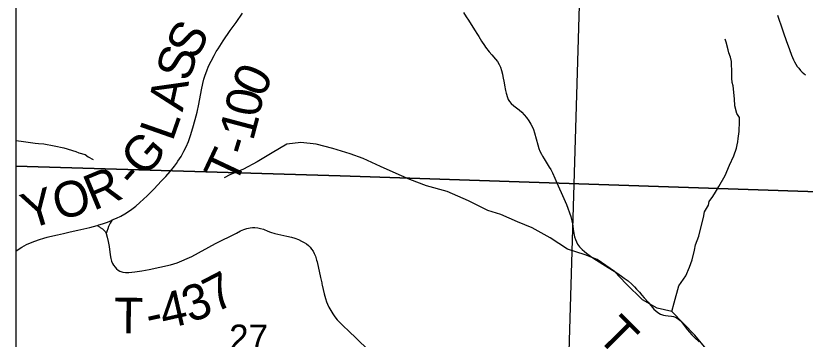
# Model space of a CAD drawing. Extents: x 6.3 to 40.3, y 9 to 31.
# Drawn here: x 8.445 to 9.705, y 27.639 to 28.156 of the extents above; entities that cross this region are included whole.
import ezdxf

# ---------------------------------------------------------------- set-up
doc = ezdxf.new("R2010")
doc.units = 0
for name, color, linetype in [('Default', 7, 'Continuous'), ('GM_X_Corporation', 7, 'Continuous'), ('GM_X_Minor_River', 7, 'Continuous'), ('GM_X_Section', 7, 'Continuous'), ('GM_X_Section_Text', 7, 'Continuous'), ('GM_X_Township_Road', 7, 'Continuous'), ('GM_X_Township_Road_Text', 7, 'Continuous'), ('SH_Cut_Line', 7, 'Continuous'), ('SH_Data', 7, 'Continuous')]:
    doc.layers.add(name, color=color, linetype=linetype)

msp = doc.modelspace()

# ---------------------------------------------------------------- linework, layer by layer
at = {"layer": 'Default'}
msp.add_lwpolyline([(13.1323, 29.9457), (8.4446, 29.9457), (8.4446, 27.9161), (8.9627, 27.9002), (9.9314, 27.8681), (10.145, 27.8635), (10.7129, 27.8423), (11.7175, 27.8106), (12.5872, 27.7766), (13.0625, 27.76), (13.0974, 28.6191), (13.1136, 29.1637), (13.1156, 29.231), (13.116, 29.2473), (13.13, 29.8856)], close=True, dxfattribs=at)
for points in [[(12.9672, 29.1426), (12.4918, 29.1593), (11.6221, 29.1933), (10.6176, 29.225), (10.0496, 29.2462), (9.8361, 29.2507), (8.8673, 29.2829), (8.4446, 29.2958), (8.4446, 23.1457)], [(12.5872, 27.7766), (11.7175, 27.8106), (10.7129, 27.8423), (10.145, 27.8635), (9.9314, 27.8681), (8.9627, 27.9002), (8.4446, 27.9161), (8.4446, 23.1457)]]:
    msp.add_lwpolyline(points, dxfattribs=at)
at = {"layer": 'GM_X_Corporation'}
msp.add_lwpolyline([(8.4446, 28.2864), (8.4446, 27.2958), (9.3175, 27.262), (9.3471, 28.2622)], close=True, dxfattribs=at)
at = {"layer": 'GM_X_Minor_River'}
for points in [[(9.4919, 27.6836), (9.4958, 27.6975), (9.5031, 27.7249), (9.5143, 27.7406), (9.5203, 27.7543), (9.5243, 27.7665), (9.5283, 27.7818), (9.5298, 27.7902), (9.5349, 27.8043), (9.5382, 27.8176), (9.5426, 27.834), (9.5444, 27.8427), (9.5504, 27.8538), (9.5518, 27.8592), (9.5574, 27.8672), (9.5619, 27.8741), (9.5671, 27.8833), (9.5772, 27.9012), (9.5843, 27.9173), (9.5909, 27.9325), (9.5954, 27.9447), (9.5961, 27.9501), (9.5972, 27.9546), (9.5982, 27.96), (9.5996, 27.9714), (9.6002, 27.9873), (9.6002, 27.9934), (9.5959, 27.9998), (9.5928, 28.0123), (9.5919, 28.0233), (9.5898, 28.0442), (9.5886, 28.0495), (9.5881, 28.0564), (9.5877, 28.0639), (9.5875, 28.0829), (9.5855, 28.0898), (9.5828, 28.0966), (9.582, 28.1015), (9.5788, 28.114), (9.5772, 28.1185)], [(8.4446, 27.9567), (8.453, 27.9557), (8.4758, 27.9525), (8.4811, 27.9522), (8.4895, 27.9515), (8.5059, 27.9482), (8.5215, 27.945), (8.5405, 27.9395), (8.5451, 27.9369), (8.5554, 27.9347), (8.5604, 27.9306), (8.568, 27.9265)], [(9.5468, 27.624), (9.529, 27.6462), (9.4919, 27.6836), (9.4688, 27.6893), (9.445, 27.7025), (9.4193, 27.7278), (9.4007, 27.7478), (9.3731, 27.767), (9.3538, 27.7742), (9.3254, 27.7833), (9.2977, 27.8014), (9.269, 27.8173), (9.2455, 27.8271), (9.219, 27.8384), (9.1982, 27.8448), (9.1675, 27.8603), (9.1331, 27.8754), (9.1005, 27.8845), (9.0737, 27.8943), (9.0472, 27.9064), (9.0267, 27.9151), (8.9991, 27.9279), (8.9783, 27.9358), (8.951, 27.9441), (8.9241, 27.9509), (8.8995, 27.9536), (8.8776, 27.9509), (8.8537, 27.9369), (8.8302, 27.923), (8.8083, 27.9113), (8.7863, 27.9018), (8.7772, 27.8973)]]:
    msp.add_lwpolyline(points, dxfattribs=at)
at = {"layer": 'GM_X_Section'}
msp.add_lwpolyline([(9.3471, 28.2622), (10.3378, 28.2352), (10.3113, 27.232), (9.3175, 27.262)], close=True, dxfattribs=at)
at = {"layer": 'GM_X_Township_Road'}
for points in [[(8.5987, 27.8299), (8.6054, 27.8327), (8.6121, 27.8359), (8.6186, 27.8396), (8.6244, 27.8432), (8.63, 27.8471), (8.6363, 27.8521), (8.6429, 27.8577), (8.6542, 27.8682), (8.6654, 27.8797), (8.6769, 27.8919), (8.684, 27.8996), (8.691, 27.9075), (8.6981, 27.9161), (8.7011, 27.9201), (8.7035, 27.9237), (8.7085, 27.9315), (8.713, 27.9397), (8.7166, 27.9469), (8.7202, 27.9555), (8.7235, 27.9649), (8.7274, 27.9773), (8.7312, 27.9904), (8.734, 28.0019), (8.7367, 28.0146), (8.7412, 28.0376), (8.7434, 28.0479), (8.745, 28.0546), (8.7469, 28.0611), (8.7494, 28.0681), (8.7525, 28.0756), (8.7563, 28.0834), (8.7611, 28.0928), (8.7645, 28.0987), (8.7675, 28.1034), (8.7758, 28.1158), (8.787, 28.1323), (8.7964, 28.1454), (8.8068, 28.1601)], [(9.1595, 28.1613), (9.1639, 28.1545), (9.1676, 28.1488), (9.1771, 28.1335), (9.1817, 28.1261), (9.1837, 28.123), (9.1883, 28.1157), (9.193, 28.1084), (9.1948, 28.1058), (9.2004, 28.0984), (9.2044, 28.0936), (9.2106, 28.0866), (9.2137, 28.0828), (9.2166, 28.078), (9.2184, 28.0741), (9.2201, 28.0688), (9.2216, 28.0627), (9.2224, 28.0591), (9.2244, 28.0487), (9.225, 28.0451), (9.2266, 28.0365), (9.2276, 28.0323), (9.2295, 28.0257), (9.2309, 28.0223), (9.2328, 28.0191), (9.2356, 28.0158), (9.2398, 28.0121), (9.2482, 28.0057), (9.2524, 28.002), (9.2562, 27.9979), (9.2598, 27.9936), (9.2638, 27.9881), (9.2671, 27.9828), (9.2698, 27.9779), (9.2712, 27.9745), (9.273, 27.9692), (9.2757, 27.9596), (9.2782, 27.95), (9.2799, 27.944), (9.2815, 27.94), (9.2837, 27.9349), (9.2854, 27.9316), (9.288, 27.9274), (9.2914, 27.9222), (9.2964, 27.9143), (9.2986, 27.9106), (9.3015, 27.9052), (9.3054, 27.8967), (9.3107, 27.8843), (9.3174, 27.8692), (9.324, 27.8546), (9.3307, 27.8353), (9.3332, 27.824), (9.3349, 27.8117), (9.3367, 27.8032), (9.3382, 27.7985), (9.3415, 27.7911), (9.3444, 27.7871), (9.3488, 27.7828), (9.3527, 27.7797), (9.3559, 27.7768), (9.3643, 27.7704), (9.3716, 27.7656), (9.3863, 27.7567), (9.4043, 27.7457), (9.4118, 27.7404), (9.4162, 27.737), (9.4221, 27.7326), (9.4282, 27.7275), (9.4326, 27.7233), (9.4359, 27.7196), (9.4402, 27.7144), (9.4443, 27.7098), (9.4481, 27.7057), (9.4541, 27.6986), (9.4633, 27.6876), (9.4664, 27.6846), (9.4698, 27.6819), (9.4741, 27.6794), (9.4787, 27.6778), (9.4818, 27.6772), (9.4861, 27.6767), (9.4917, 27.6762), (9.4947, 27.6756), (9.4977, 27.6746), (9.5004, 27.6732), (9.5029, 27.6716), (9.5053, 27.6696), (9.5074, 27.6674), (9.5119, 27.6614), (9.5167, 27.6549), (9.5203, 27.6506), (9.524, 27.6465), (9.5288, 27.6416), (9.5358, 27.6354)], [(9.6606, 28.1569), (9.6636, 28.1489), (9.6663, 28.1413), (9.6706, 28.129), (9.6748, 28.1167), (9.6798, 28.102), (9.683, 28.0932), (9.6846, 28.0893), (9.6861, 28.0858), (9.6879, 28.0822), (9.6901, 28.0785), (9.6924, 28.0752), (9.6947, 28.0723), (9.6977, 28.0688), (9.7003, 28.0662), (9.7029, 28.0637), (9.7052, 28.0617)], [(8.5743, 27.8212), (8.577, 27.822), (8.5829, 27.8238), (8.5894, 27.8261), (8.5963, 27.8288), (8.5987, 27.8299)], [(8.5987, 27.8299), (8.5955, 27.8248), (8.5942, 27.8227), (8.5926, 27.8193), (8.5913, 27.8158), (8.5899, 27.8116), (8.589, 27.8085)], [(8.4446, 27.7802), (8.45, 27.7837), (8.4542, 27.7863), (8.4617, 27.7905), (8.4679, 27.7935), (8.4748, 27.7963), (8.4824, 27.7989), (8.4895, 27.801), (8.4949, 27.8024), (8.4992, 27.8034), (8.5112, 27.8063), (8.5209, 27.8085), (8.5312, 27.8108), (8.5439, 27.8137), (8.5626, 27.818), (8.5743, 27.8212)], [(8.5743, 27.8212), (8.5783, 27.8187), (8.5793, 27.8181), (8.5829, 27.8156), (8.5852, 27.8136), (8.5872, 27.8115), (8.589, 27.8085)], [(8.589, 27.8085), (8.5905, 27.8026), (8.5921, 27.7953), (8.5935, 27.7873), (8.5951, 27.7744), (8.5962, 27.7682), (8.5973, 27.764), (8.5988, 27.7606), (8.6004, 27.758), (8.6032, 27.7546), (8.6056, 27.7518), (8.6079, 27.7497), (8.6107, 27.7482), (8.6156, 27.7468), (8.6199, 27.7462), (8.6251, 27.746), (8.6348, 27.747), (8.646, 27.7485), (8.6574, 27.751), (8.6914, 27.7585), (8.7022, 27.7616), (8.7258, 27.7715), (8.7636, 27.7924), (8.7971, 27.8091), (8.8036, 27.8125), (8.8088, 27.8147), (8.8134, 27.8163), (8.8188, 27.8175), (8.8225, 27.8179), (8.8262, 27.8179), (8.8311, 27.8174), (8.8353, 27.8165), (8.84, 27.815), (8.8469, 27.8121), (8.8515, 27.8103), (8.8581, 27.8085), (8.8677, 27.8061), (8.8774, 27.804), (8.8847, 27.8023), (8.89, 27.8007), (8.8958, 27.7986), (8.9009, 27.7963), (8.9052, 27.794), (8.9087, 27.7916), (8.912, 27.7889), (8.9146, 27.7863), (8.9169, 27.7835), (8.9192, 27.78), (8.9211, 27.7763), (8.9229, 27.7719), (8.9241, 27.768), (8.9248, 27.7658), (8.9256, 27.7629), (8.9312, 27.7378), (8.9331, 27.7296), (8.9334, 27.7278), (8.9338, 27.7256), (8.937, 27.7119), (8.9389, 27.7046), (8.9408, 27.699), (8.9421, 27.6956), (8.9445, 27.6906), (8.9474, 27.6851), (8.9507, 27.6798), (8.9539, 27.6753), (8.9579, 27.6705), (8.9625, 27.6655), (8.9678, 27.6602), (8.976, 27.6527), (8.9887, 27.6405), (9.0076, 27.6222)]]:
    msp.add_lwpolyline(points, dxfattribs=at)
at = {"layer": 'SH_Cut_Line'}
msp.add_lwpolyline([(12.9672, 29.1426), (12.4918, 29.1593), (11.6221, 29.1933), (10.6176, 29.225), (10.0496, 29.2462), (9.8361, 29.2507), (8.8673, 29.2829), (8.4446, 29.2958), (8.4446, 23.1457)], dxfattribs=at)
at = {"layer": 'SH_Data'}
msp.add_line((8.4446, 29.9457), (8.4446, 23.1457), dxfattribs=at)

# ---------------------------------------------------------------- texts
at = {"layer": 'GM_X_Section_Text'}
msp.add_text('27', height=0.04186, rotation=0, dxfattribs=at).set_placement((8.7852, 27.621))
at = {"layer": 'GM_X_Township_Road_Text'}
for s, rotation, p in [('S', 61.586, (8.7314, 28.0831)), ('S', 72.5011, (8.721, 28.0491)), ('0', 65.0642, (8.8389, 28.0232)), ('A', 77.8941, (8.7109, 28.0016)), ('0', 78.5997, (8.8331, 27.9922)), ('L', 70.6866, (8.6947, 27.954)), ('1', 75.1578, (8.8233, 27.9548)), ('G', 48.8285, (8.65, 27.896)), ('-', 73.2107, (8.816, 27.9304)), ('T', 64.7537, (8.7945, 27.8834)), ('R', 22.6785, (8.5687, 27.8442)), ('-', 48.4926, (8.6343, 27.8783)), ('O', 14.0521, (8.5113, 27.8291)), ('Y', 16.9281, (8.4642, 27.8147)), ('7', 27.529, (8.763, 27.6806)), ('3', 20.2128, (8.7229, 27.6653)), ('4', 12.8341, (8.6812, 27.6552)), ('T', 359.1686, (8.6012, 27.6493)), ('-', 12.4401, (8.658, 27.6501)), ('T', 314.9061, (9.3702, 27.6424))]:
    msp.add_text(s, height=0.0568, rotation=rotation, dxfattribs=at).set_placement(p)

doc.saveas('drawing.dxf')
